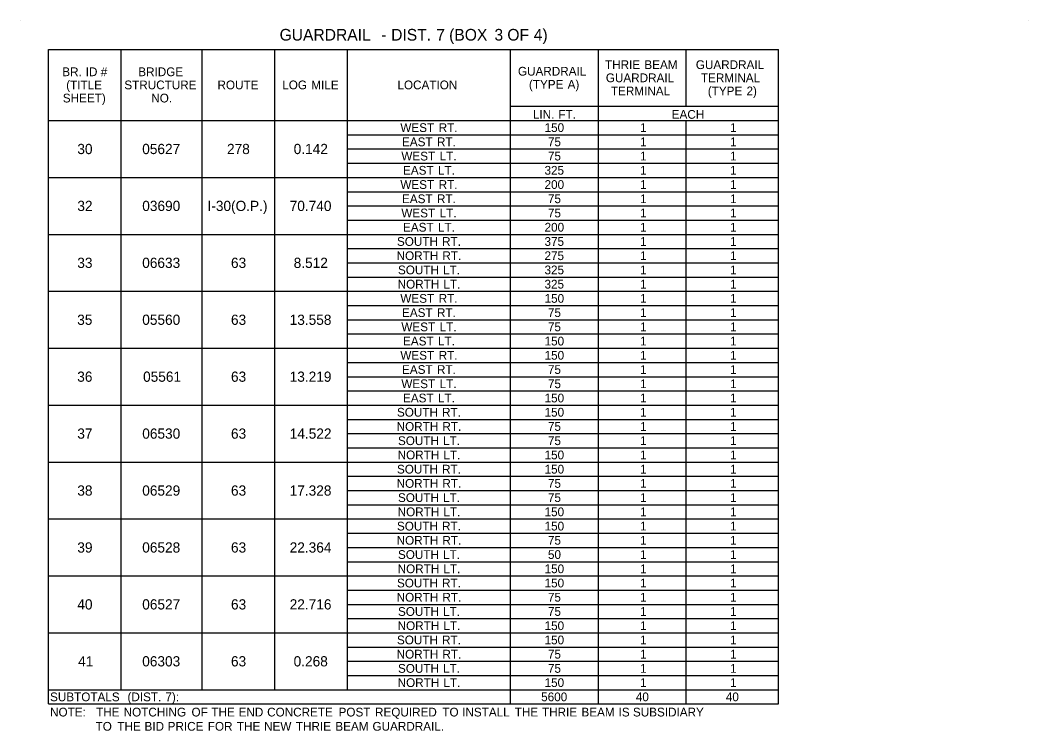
# Model space of a CAD drawing. Extents: x 544250 to 1930787, y -1948365 to 596640.
# Drawn here: x 550002 to 550693, y -1946712 to -1946225 of the extents above; entities that cross this region are included whole.
import ezdxf

# ---------------------------------------------------------------- set-up
doc = ezdxf.new("R2010")
doc.units = 0
doc.layers.add('Default', color=7, linetype='Continuous')

msp = doc.modelspace()

# ---------------------------------------------------------------- linework, layer by layer
at = {"layer": 'Default'}
for p, q in [((550002.05, -1946225.02), (550002.05, -1946225.02)), ((550693.2, -1946225.02), (550693.2, -1946225.02)), ((550021.55, -1946245.01), (550521.73, -1946245.01)), ((550021.55, -1946693.51), (550021.55, -1946245.01)), ((550021.55, -1946693.51), (550021.55, -1946245.01)), ((550071.28, -1946683.76), (550071.28, -1946245.01)), ((550126.85, -1946683.76), (550126.85, -1946245.01)), ((550176.58, -1946683.76), (550176.58, -1946245.01)), ((550226.3, -1946683.76), (550226.3, -1946245.01)), ((550337.94, -1946693.51), (550337.94, -1946245.01)), ((550398.39, -1946693.51), (550398.39, -1946245.01)), ((550458.35, -1946284.01), (550458.35, -1946245.01)), ((550521.73, -1946693.51), (550521.73, -1946245.01)), ((550337.94, -1946284.01), (550521.73, -1946284.01)), ((550398.39, -1946293.76), (550398.39, -1946284.01)), ((550521.73, -1946293.76), (550521.73, -1946284.01)), ((550021.55, -1946293.76), (550521.73, -1946293.76)), ((550458.35, -1946693.51), (550458.35, -1946293.76)), ((550226.3, -1946303.51), (550521.73, -1946303.51)), ((550226.3, -1946313.26), (550521.73, -1946313.26)), ((550226.3, -1946323.01), (550521.73, -1946323.01)), ((550021.55, -1946332.76), (550521.73, -1946332.76)), ((550226.3, -1946342.51), (550521.73, -1946342.51)), ((550226.3, -1946352.26), (550521.73, -1946352.26)), ((550226.3, -1946362.01), (550521.73, -1946362.01)), ((550021.55, -1946371.76), (550521.73, -1946371.76)), ((550226.3, -1946381.51), (550521.73, -1946381.51)), ((550226.3, -1946391.26), (550521.73, -1946391.26)), ((550226.3, -1946401.01), (550521.73, -1946401.01)), ((550021.55, -1946410.76), (550521.73, -1946410.76)), ((550226.3, -1946420.51), (550521.73, -1946420.51)), ((550226.3, -1946430.26), (550521.73, -1946430.26)), ((550226.3, -1946440.01), (550521.73, -1946440.01)), ((550021.55, -1946449.76), (550521.73, -1946449.76)), ((550226.3, -1946459.51), (550521.73, -1946459.51)), ((550226.3, -1946469.26), (550521.73, -1946469.26)), ((550226.3, -1946479.01), (550521.73, -1946479.01)), ((550021.55, -1946488.76), (550521.73, -1946488.76)), ((550226.3, -1946498.51), (550521.73, -1946498.51)), ((550226.3, -1946508.26), (550521.73, -1946508.26)), ((550226.3, -1946518.01), (550521.73, -1946518.01)), ((550021.55, -1946527.76), (550521.73, -1946527.76)), ((550521.73, -1946644.76), (550521.73, -1946527.76)), ((550226.3, -1946537.51), (550521.73, -1946537.51)), ((550226.3, -1946547.26), (550521.73, -1946547.26)), ((550226.3, -1946557.01), (550521.73, -1946557.01)), ((550021.55, -1946566.76), (550521.73, -1946566.76)), ((550226.3, -1946576.51), (550521.73, -1946576.51)), ((550226.3, -1946586.26), (550521.73, -1946586.26)), ((550226.3, -1946596.01), (550521.73, -1946596.01)), ((550021.55, -1946605.76), (550521.73, -1946605.76)), ((550226.3, -1946615.51), (550521.73, -1946615.51)), ((550226.3, -1946625.26), (550521.73, -1946625.26)), ((550226.3, -1946635.01), (550521.73, -1946635.01)), ((550021.55, -1946644.76), (550521.73, -1946644.76)), ((550226.3, -1946654.51), (550521.73, -1946654.51)), ((550226.3, -1946664.26), (550521.73, -1946664.26)), ((550226.3, -1946674.01), (550521.73, -1946674.01)), ((550021.55, -1946683.76), (550521.73, -1946683.76)), ((550398.39, -1946693.51), (550398.39, -1946683.76)), ((550458.35, -1946693.51), (550458.35, -1946683.76)), ((550521.73, -1946693.51), (550521.73, -1946683.76)), ((550021.55, -1946693.51), (550521.73, -1946693.51))]:
    msp.add_line(p, q, dxfattribs=at)

# ---------------------------------------------------------------- texts
for s, height, p in [('GUARDRAIL', 8, (550179.82, -1946239.01)), (' DIST.', 8, (550253.3, -1946239.01)), (' 7', 8, (550284.2, -1946239.01)), (' (BOX', 8, (550293.02, -1946239.01)), (' 3', 8, (550324.06, -1946239.01)), (' OF', 8, (550332.89, -1946239.01)), (' 4)', 8, (550351, -1946239.01)), (' -', 8, (550246.55, -1946239.01)), ('THRIE', 6, (550402.8, -1946258.51)), (' BEAM', 6, (550427.53, -1946258.51)), ('GUARDRAIL', 6, (550465.02, -1946258.51)), ('BR.', 6, (550030.89, -1946263.38)), (' ID', 6, (550044.75, -1946263.38)), (' #', 6, (550055.05, -1946263.38)), ('BRIDGE', 6, (550082.97, -1946263.38)), ('GUARDRAIL', 6, (550343.14, -1946263.01)), ('(TITLE', 6, (550033.59, -1946272.38)), ('STRUCTURE', 6, (550073.42, -1946272.38)), ('ROUTE', 6, (550137.25, -1946272.38)), ('LOG', 6, (550181.64, -1946272.38)), (' MILE', 6, (550199.3, -1946272.38)), ('LOCATION', 6, (550260.57, -1946272.38)), ('(TYPE', 6, (550350.66, -1946272.01)), (' A)', 6, (550374.93, -1946272.01)), ('GUARDRAIL', 6, (550403.35, -1946267.51)), ('TERMINAL', 6, (550468.51, -1946267.51)), ('SHEET)', 6, (550031.26, -1946281.38)), ('TERMINAL', 6, (550406.84, -1946276.51)), ('(TYPE', 6, (550473.23, -1946276.51)), (' 2)', 6, (550497.51, -1946276.51)), ('NO.', 6, (550091.9, -1946281.38)), ('LIN.', 6, (550353.38, -1946292.56)), (' FT.', 6, (550368.63, -1946292.56)), ('EACH', 6, (550448.5, -1946292.56)), ('WEST', 6, (550262.55, -1946301.63)), (' RT.', 6, (550286.6, -1946301.63)), ('150', 6, (550361.38, -1946301.63)), ('1', 6, (550426.81, -1946301.63)), ('1', 6, (550488.48, -1946301.63)), ('30', 7, (550041.22, -1946316.76)), ('05627', 7, (550085.69, -1946316.76)), ('278', 7, (550143.78, -1946316.76)), ('0.142', 7, (550189.47, -1946316.76)), ('EAST', 6, (550263.71, -1946311.38)), (' RT.', 6, (550285.44, -1946311.38)), ('75', 6, (550363.67, -1946311.38)), ('1', 6, (550426.81, -1946311.38)), ('1', 6, (550488.48, -1946311.38)), ('WEST', 6, (550263.24, -1946321.13)), (' LT.', 6, (550287.29, -1946321.13)), ('75', 6, (550363.67, -1946321.13)), ('1', 6, (550426.81, -1946321.13)), ('1', 6, (550488.48, -1946321.13)), ('EAST', 6, (550264.4, -1946330.88)), (' LT.', 6, (550286.13, -1946330.88)), ('325', 6, (550361.34, -1946330.88)), ('1', 6, (550426.81, -1946330.88)), ('1', 6, (550488.48, -1946330.88)), ('WEST', 6, (550262.55, -1946340.63)), (' RT.', 6, (550286.6, -1946340.63)), ('200', 6, (550361.38, -1946340.63)), ('1', 6, (550426.81, -1946340.63)), ('1', 6, (550488.48, -1946340.63)), ('32', 7, (550041.22, -1946355.76)), ('03690', 7, (550085.71, -1946355.76)), ('I-30(O.P.)', 7, (550130.43, -1946355.76)), ('70.740', 7, (550186.73, -1946355.76)), ('EAST', 6, (550263.71, -1946350.38)), (' RT.', 6, (550285.44, -1946350.38)), ('75', 6, (550363.67, -1946350.38)), ('1', 6, (550426.81, -1946350.38)), ('1', 6, (550488.48, -1946350.38)), ('WEST', 6, (550263.24, -1946360.13)), (' LT.', 6, (550287.29, -1946360.13)), ('75', 6, (550363.67, -1946360.13)), ('1', 6, (550426.81, -1946360.13)), ('1', 6, (550488.48, -1946360.13)), ('EAST', 6, (550264.4, -1946369.88)), (' LT.', 6, (550286.13, -1946369.88)), ('200', 6, (550361.38, -1946369.88)), ('1', 6, (550426.81, -1946369.88)), ('1', 6, (550488.48, -1946369.88)), ('SOUTH', 6, (550260.24, -1946379.63)), (' RT.', 6, (550288.91, -1946379.63)), ('375', 6, (550361.34, -1946379.63)), ('1', 6, (550426.81, -1946379.63)), ('1', 6, (550488.48, -1946379.63)), ('NORTH', 6, (550260.01, -1946389.38)), (' RT.', 6, (550289.14, -1946389.38)), ('275', 6, (550361.34, -1946389.38)), ('1', 6, (550426.81, -1946389.38)), ('1', 6, (550488.48, -1946389.38)), ('33', 7, (550041.19, -1946394.76)), ('06633', 7, (550085.68, -1946394.76)), ('63', 7, (550146.5, -1946394.76)), ('8.512', 7, (550189.47, -1946394.76)), ('SOUTH', 6, (550260.93, -1946399.13)), (' LT.', 6, (550289.6, -1946399.13)), ('325', 6, (550361.34, -1946399.13)), ('1', 6, (550426.81, -1946399.13)), ('1', 6, (550488.48, -1946399.13)), ('NORTH', 6, (550260.7, -1946408.88)), (' LT.', 6, (550289.83, -1946408.88)), ('325', 6, (550361.34, -1946408.88)), ('1', 6, (550426.81, -1946408.88)), ('1', 6, (550488.48, -1946408.88)), ('WEST', 6, (550262.55, -1946418.63)), (' RT.', 6, (550286.6, -1946418.63)), ('150', 6, (550361.38, -1946418.63)), ('1', 6, (550426.81, -1946418.63)), ('1', 6, (550488.48, -1946418.63)), ('35', 7, (550041.13, -1946433.76)), ('05560', 7, (550085.71, -1946433.76)), ('63', 7, (550146.5, -1946433.76)), ('13.558', 7, (550186.71, -1946433.76)), ('EAST', 6, (550263.71, -1946428.38)), (' RT.', 6, (550285.44, -1946428.38)), ('75', 6, (550363.67, -1946428.38)), ('1', 6, (550426.81, -1946428.38)), ('1', 6, (550488.48, -1946428.38)), ('WEST', 6, (550263.24, -1946438.13)), (' LT.', 6, (550287.29, -1946438.13)), ('75', 6, (550363.67, -1946438.13)), ('1', 6, (550426.81, -1946438.13)), ('1', 6, (550488.48, -1946438.13)), ('EAST', 6, (550264.4, -1946447.88)), (' LT.', 6, (550286.13, -1946447.88)), ('150', 6, (550361.38, -1946447.88)), ('1', 6, (550426.81, -1946447.88)), ('1', 6, (550488.48, -1946447.88)), ('WEST', 6, (550262.55, -1946457.63)), (' RT.', 6, (550286.6, -1946457.63)), ('150', 6, (550361.38, -1946457.63)), ('1', 6, (550426.81, -1946457.63)), ('1', 6, (550488.48, -1946457.63)), ('EAST', 6, (550263.71, -1946467.38)), (' RT.', 6, (550285.44, -1946467.38)), ('75', 6, (550363.67, -1946467.38)), ('1', 6, (550426.81, -1946467.38)), ('1', 6, (550488.48, -1946467.38)), ('36', 7, (550041.15, -1946472.76)), ('05561', 7, (550086.27, -1946472.76)), ('63', 7, (550146.5, -1946472.76)), ('13.219', 7, (550186.71, -1946472.76)), ('WEST', 6, (550263.24, -1946477.13)), (' LT.', 6, (550287.29, -1946477.13)), ('75', 6, (550363.67, -1946477.13)), ('1', 6, (550426.81, -1946477.13)), ('1', 6, (550488.48, -1946477.13)), ('EAST', 6, (550264.4, -1946486.88)), (' LT.', 6, (550286.13, -1946486.88)), ('150', 6, (550361.38, -1946486.88)), ('1', 6, (550426.81, -1946486.88)), ('1', 6, (550488.48, -1946486.88)), ('SOUTH', 6, (550260.24, -1946496.63)), (' RT.', 6, (550288.91, -1946496.63)), ('150', 6, (550361.38, -1946496.63)), ('1', 6, (550426.81, -1946496.63)), ('1', 6, (550488.48, -1946496.63)), ('NORTH', 6, (550260.01, -1946506.38)), (' RT.', 6, (550289.14, -1946506.38)), ('75', 6, (550363.67, -1946506.38)), ('1', 6, (550426.81, -1946506.38)), ('1', 6, (550488.48, -1946506.38)), ('37', 7, (550041.19, -1946511.76)), ('06530', 7, (550085.71, -1946511.76)), ('63', 7, (550146.5, -1946511.76)), ('14.522', 7, (550186.75, -1946511.76)), ('SOUTH', 6, (550260.93, -1946516.13)), (' LT.', 6, (550289.6, -1946516.13)), ('75', 6, (550363.67, -1946516.13)), ('1', 6, (550426.81, -1946516.13)), ('1', 6, (550488.48, -1946516.13)), ('NORTH', 6, (550260.7, -1946525.88)), (' LT.', 6, (550289.83, -1946525.88)), ('150', 6, (550361.38, -1946525.88)), ('1', 6, (550426.81, -1946525.88)), ('1', 6, (550488.48, -1946525.88)), ('SOUTH', 6, (550260.24, -1946535.63)), (' RT.', 6, (550288.91, -1946535.63)), ('150', 6, (550361.38, -1946535.63)), ('1', 6, (550426.81, -1946535.63)), ('1', 6, (550488.48, -1946535.63)), ('38', 7, (550041.2, -1946550.76)), ('06529', 7, (550085.7, -1946550.76)), ('63', 7, (550146.5, -1946550.76)), ('17.328', 7, (550186.71, -1946550.76)), ('NORTH', 6, (550260.01, -1946545.38)), (' RT.', 6, (550289.14, -1946545.38)), ('75', 6, (550363.67, -1946545.38)), ('1', 6, (550426.81, -1946545.38)), ('1', 6, (550488.48, -1946545.38)), ('SOUTH', 6, (550260.93, -1946555.13)), (' LT.', 6, (550289.6, -1946555.13)), ('75', 6, (550363.67, -1946555.13)), ('1', 6, (550426.81, -1946555.13)), ('1', 6, (550488.48, -1946555.13)), ('NORTH', 6, (550260.7, -1946564.88)), (' LT.', 6, (550289.83, -1946564.88)), ('150', 6, (550361.38, -1946564.88)), ('1', 6, (550426.81, -1946564.88)), ('1', 6, (550488.48, -1946564.88)), ('SOUTH', 6, (550260.24, -1946574.63)), (' RT.', 6, (550288.91, -1946574.63)), ('150', 6, (550361.38, -1946574.63)), ('1', 6, (550426.81, -1946574.63)), ('1', 6, (550488.48, -1946574.63)), ('NORTH', 6, (550260.01, -1946584.38)), (' RT.', 6, (550289.14, -1946584.38)), ('75', 6, (550363.67, -1946584.38)), ('1', 6, (550426.81, -1946584.38)), ('1', 6, (550488.48, -1946584.38)), ('39', 7, (550041.21, -1946589.76)), ('06528', 7, (550085.69, -1946589.76)), ('63', 7, (550146.5, -1946589.76)), ('22.364', 7, (550186.73, -1946589.76)), ('SOUTH', 6, (550260.93, -1946594.13)), (' LT.', 6, (550289.6, -1946594.13)), ('50', 6, (550363.71, -1946594.13)), ('1', 6, (550426.81, -1946594.13)), ('1', 6, (550488.48, -1946594.13)), ('NORTH', 6, (550260.7, -1946603.88)), (' LT.', 6, (550289.83, -1946603.88)), ('150', 6, (550361.38, -1946603.88)), ('1', 6, (550426.81, -1946603.88)), ('1', 6, (550488.48, -1946603.88)), ('SOUTH', 6, (550260.24, -1946613.63)), (' RT.', 6, (550288.91, -1946613.63)), ('150', 6, (550361.38, -1946613.63)), ('1', 6, (550426.81, -1946613.63)), ('1', 6, (550488.48, -1946613.63)), ('NORTH', 6, (550260.01, -1946623.38)), (' RT.', 6, (550289.14, -1946623.38)), ('75', 6, (550363.67, -1946623.38)), ('1', 6, (550426.81, -1946623.38)), ('1', 6, (550488.48, -1946623.38)), ('40', 7, (550041.22, -1946628.76)), ('06527', 7, (550085.69, -1946628.76)), ('63', 7, (550146.5, -1946628.76)), ('22.716', 7, (550186.71, -1946628.76)), ('SOUTH', 6, (550260.93, -1946633.13)), (' LT.', 6, (550289.6, -1946633.13)), ('75', 6, (550363.67, -1946633.13)), ('1', 6, (550426.81, -1946633.13)), ('1', 6, (550488.48, -1946633.13)), ('NORTH', 6, (550260.7, -1946642.88)), (' LT.', 6, (550289.83, -1946642.88)), ('150', 6, (550361.38, -1946642.88)), ('1', 6, (550426.81, -1946642.88)), ('1', 6, (550488.48, -1946642.88)), ('SOUTH', 6, (550260.24, -1946652.63)), (' RT.', 6, (550288.91, -1946652.63)), ('150', 6, (550361.38, -1946652.63)), ('1', 6, (550426.81, -1946652.63)), ('1', 6, (550488.48, -1946652.63)), ('41', 7, (550041.77, -1946667.76)), ('06303', 7, (550085.68, -1946667.76)), ('63', 7, (550146.5, -1946667.76)), ('0.268', 7, (550189.43, -1946667.76)), ('NORTH', 6, (550260.01, -1946662.38)), (' RT.', 6, (550289.14, -1946662.38)), ('75', 6, (550363.67, -1946662.38)), ('1', 6, (550426.81, -1946662.38)), ('1', 6, (550488.48, -1946662.38)), ('SOUTH', 6, (550260.93, -1946672.13)), (' LT.', 6, (550289.6, -1946672.13)), ('75', 6, (550363.67, -1946672.13)), ('1', 6, (550426.81, -1946672.13)), ('1', 6, (550488.48, -1946672.13)), ('NORTH', 6, (550260.7, -1946681.88)), (' LT.', 6, (550289.83, -1946681.88)), ('150', 6, (550361.38, -1946681.88)), ('1', 6, (550426.81, -1946681.88)), ('1', 6, (550488.48, -1946681.88)), ('SUBTOTALS', 6, (550022.53, -1946691.63)), (' (DIST.', 6, (550073.35, -1946691.63)), (' 7):', 6, (550099.32, -1946691.63)), ('5600', 6, (550359.05, -1946691.63)), ('40', 6, (550423.92, -1946691.63)), ('40', 6, (550485.59, -1946691.63)), ('NOTE:', 6, (550022.53, -1946702.06)), ('   THE', 6, (550047.42, -1946702.06)), (' NOTCHING', 6, (550070.72, -1946702.06)), (' OF', 6, (550117.23, -1946702.06)), (' THE', 6, (550130.82, -1946702.06)), (' END', 6, (550149.47, -1946702.06)), (' CONCRETE', 6, (550169.05, -1946702.06)), (' POST', 6, (550217.98, -1946702.06)), (' REQUIRED', 6, (550242.97, -1946702.06)), (' TO', 6, (550289.1, -1946702.06)), (' INSTALL', 6, (550302.7, -1946702.06)), (' THE', 6, (550338.74, -1946702.06)), (' THRIE', 6, (550357.39, -1946702.06)), (' BEAM', 6, (550384.42, -1946702.06)), (' IS', 6, (550409.88, -1946702.06)), (' SUBSIDIARY', 6, (550419.69, -1946702.06)), ('              TO', 6, (550022.53, -1946711.81)), (' THE', 6, (550066.38, -1946711.81)), (' BID', 6, (550085.03, -1946711.81)), (' PRICE', 6, (550100.89, -1946711.81)), (' FOR', 6, (550128.39, -1946711.81)), (' THE', 6, (550148.3, -1946711.81)), (' NEW', 6, (550166.95, -1946711.81)), (' THRIE', 6, (550188.74, -1946711.81)), (' BEAM', 6, (550215.78, -1946711.81)), (' GUARDRAIL.', 6, (550241.24, -1946711.81))]:
    msp.add_text(s, height=height, dxfattribs=at).set_placement(p)

doc.saveas('drawing.dxf')
